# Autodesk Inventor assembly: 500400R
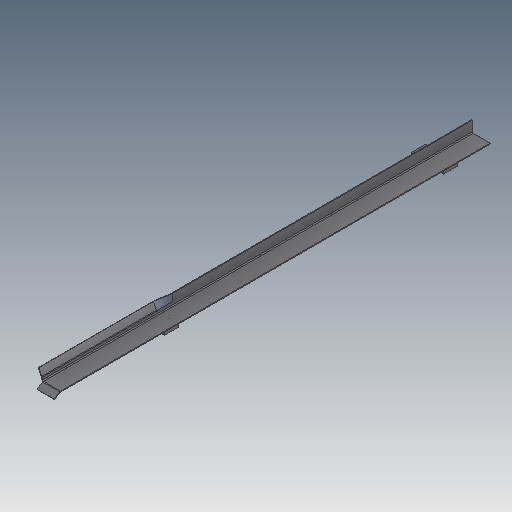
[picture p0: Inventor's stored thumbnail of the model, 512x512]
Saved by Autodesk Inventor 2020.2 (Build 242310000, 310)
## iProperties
Created: 2000-01
Part Number: 500400R
Description: WMT-CP,SS,XX,GUIDE,ANGLE
Document SubType Name: Assembly
Designer: sspink
Mass: 1309.91 g
Surface Area: 3546.89 cm^2
Volume: 575.176 cm^3
Density: 2.27741 g/cm^3
Control State: 0
Checked Out: False
Master: False
Shininess: 0.0
Length Units: 11269
Angle Units: 11279
Time Units: 11290
Mass Units: 11283
Length Display Precision: 3
Angle Display Precision: 2
Compacted: True
Dimensions: 53,1x1545,7x114 mm
Mass: 1,31 kg
Density: 0.0
Volumn: 0.0
Area: 0.0
PropertySet Name: Model Information
Author: sspink
Revision Number: -
Title: WMT-CP,SS,XX,GUIDE,ANGLE
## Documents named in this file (4)
- D:\07 - DEMODATEN\OTX 2019 - Dataset - UPDATE - Dez2019\Designs\07-Packing machine\500400R.iam
- D:\07 - DEMODATEN\OTX 2019 - Dataset - UPDATE - Dez2019\Designs\07-Packing machine\Parts\ADSK-011382.ipt
- D:\07 - DEMODATEN\OTX 2019 - Dataset - UPDATE - Dez2019\Designs\07-Packing machine\Parts\ADSK-011384.ipt
- D:\07 - DEMODATEN\OTX 2019 - Dataset - UPDATE - Dez2019\Designs\07-Packing machine\Parts\ADSK-011363.ipt
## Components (4 placed, 3 different names)
1. ADSK-011382:1 — Passend:8, Fluchtend:6, Fluchtend:7, Passend:9, Fluchtend:8
2. ADSK-011384:1
3. ADSK-011363:3 — Passend:8, Fluchtend:6, Fluchtend:7, Fluchtend:9
4. ADSK-011363:4 — Passend:9, Fluchtend:8, Fluchtend:9
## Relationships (6: Flush 4, Mate 2)
- Passend:8 [Mate]: ADSK-011382:1 ↔ ADSK-011363:3
- Fluchtend:6 [Flush]: ADSK-011382:1 ↔ ADSK-011363:3
- Fluchtend:7 [Flush]: ADSK-011382:1 ↔ ADSK-011363:3
- Passend:9 [Mate]: ADSK-011382:1 ↔ ADSK-011363:4
- Fluchtend:8 [Flush]: ADSK-011382:1 ↔ ADSK-011363:4
- Fluchtend:9 [Flush]: ADSK-011363:3 ↔ ADSK-011363:4
